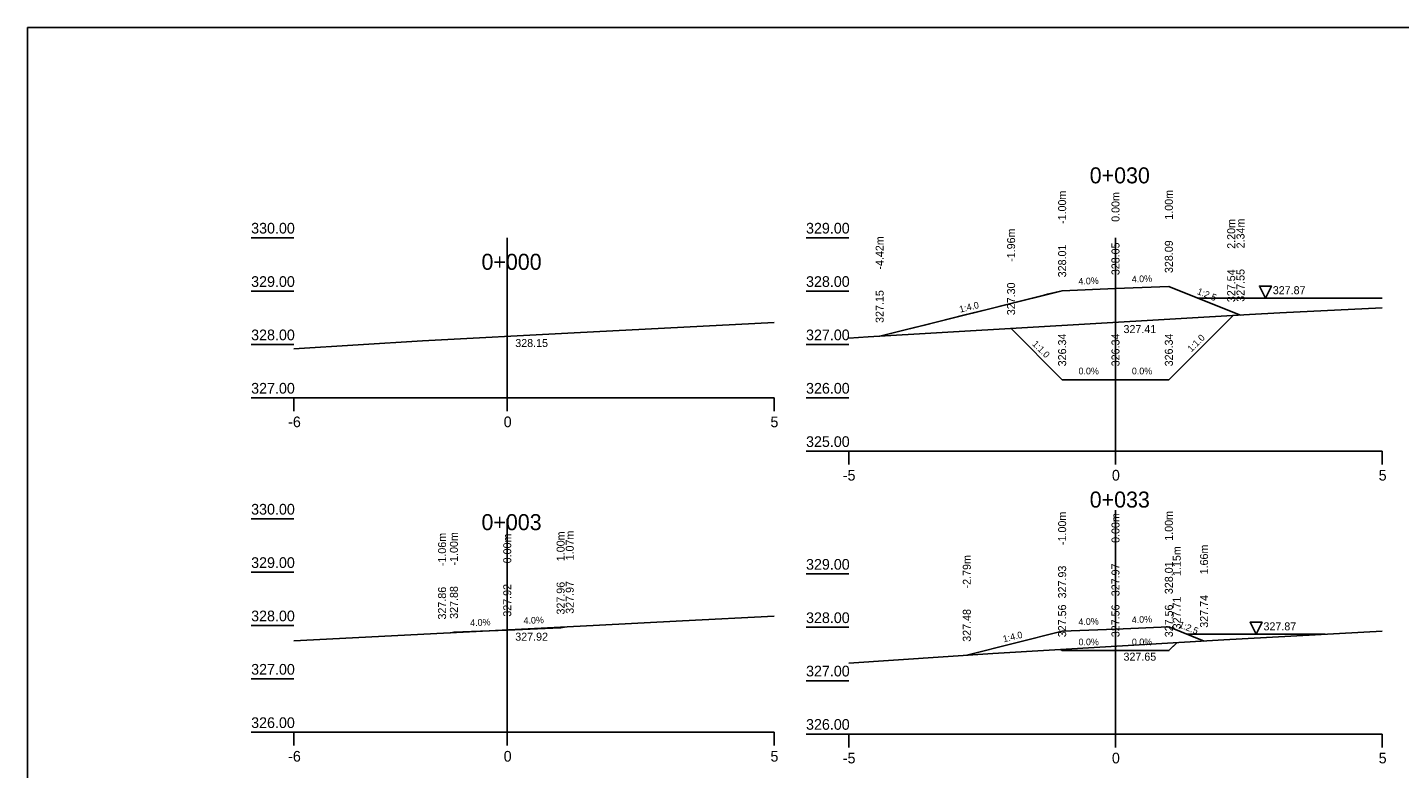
# Model space of a CAD drawing. Extents: x -560209.6 to -560167.6, y -1162747.5 to -1162717.8.
# Drawn here: x -560209.56 to -560183.84, y -1162731.68 to -1162717.79 of the extents above; entities that cross this region are included whole.
import ezdxf

# ---------------------------------------------------------------- set-up
doc = ezdxf.new("R2010")
doc.units = 0
for name, color, linetype in [('16', 7, 'Continuous'), ('21', 7, 'Continuous'), ('28', 7, 'Continuous'), ('59', 7, 'Continuous'), ('Body pricny rez', 7, 'Continuous'), ('Popis pricneho profilu', 7, 'Continuous')]:
    doc.layers.add(name, color=color, linetype=linetype)

msp = doc.modelspace()

# ---------------------------------------------------------------- linework, layer by layer
for p, q in [((-560167.561, -1162717.787), (-560209.561, -1162717.787)), ((-560209.561, -1162717.787), (-560209.561, -1162747.487))]:
    msp.add_line(p, q)
for points in [[(-560193.588, -1162723.575), (-560192.937, -1162723.412), (-560192.748, -1162723.365), (-560192.017, -1162723.182), (-560191.572, -1162723.071), (-560191.177, -1162722.972), (-560190.507, -1162722.805), (-560190.44, -1162722.788), (-560190.168, -1162722.72), (-560189.168, -1162722.68), (-560188.168, -1162722.64), (-560187.716, -1162722.821), (-560186.825, -1162723.177)], [(-560189.168, -1162722.68), (-560190.168, -1162722.72)], [(-560189.168, -1162722.68), (-560188.168, -1162722.64)], [(-560188.168, -1162722.64), (-560186.825, -1162723.177)], [(-560190.168, -1162722.72), (-560193.588, -1162723.575)], [(-560187.619, -1162722.859), (-560184.168, -1162722.859)], [(-560194.168, -1162723.612), (-560193.806, -1162723.588), (-560186.657, -1162723.167), (-560186.087, -1162723.135), (-560184.168, -1162723.044)], [(-560191.125, -1162723.43), (-560190.168, -1162724.388), (-560189.168, -1162724.388), (-560188.168, -1162724.388), (-560186.965, -1162723.185)], [(-560188.168, -1162724.388), (-560186.965, -1162723.185)], [(-560204.568, -1162723.813), (-560202.154, -1162723.657), (-560199.315, -1162723.512), (-560195.568, -1162723.317)], [(-560190.168, -1162724.388), (-560191.125, -1162723.43)], [(-560189.168, -1162724.388), (-560190.168, -1162724.388)], [(-560189.168, -1162724.388), (-560188.168, -1162724.388)], [(-560204.568, -1162729.283), (-560198.958, -1162728.997), (-560197.286, -1162728.91), (-560195.568, -1162728.821)], [(-560201.623, -1162729.133), (-560201.568, -1162729.12), (-560200.568, -1162729.08), (-560199.568, -1162729.04), (-560199.494, -1162729.025)], [(-560201.568, -1162729.12), (-560201.623, -1162729.133)], [(-560200.568, -1162729.08), (-560201.568, -1162729.12)], [(-560200.568, -1162729.08), (-560199.568, -1162729.04)], [(-560199.568, -1162729.04), (-560199.494, -1162729.025)], [(-560194.168, -1162729.699), (-560191.468, -1162729.517), (-560187.138, -1162729.265), (-560184.168, -1162729.099)], [(-560190.168, -1162729.103), (-560191.955, -1162729.55)], [(-560189.168, -1162729.063), (-560190.168, -1162729.103)], [(-560189.168, -1162729.063), (-560188.168, -1162729.023)], [(-560188.168, -1162729.023), (-560187.508, -1162729.287)], [(-560190.19, -1162729.443), (-560190.168, -1162729.465), (-560189.278, -1162729.465), (-560189.168, -1162729.465), (-560188.278, -1162729.465), (-560188.168, -1162729.465), (-560188.132, -1162729.428), (-560188.02, -1162729.317)], [(-560188.168, -1162729.465), (-560188.02, -1162729.317)], [(-560187.827, -1162729.159), (-560185.239, -1162729.159)], [(-560189.168, -1162729.465), (-560190.168, -1162729.465)], [(-560189.168, -1162729.465), (-560188.168, -1162729.465)]]:
    msp.add_lwpolyline(points)
for points in [[(-560186.359, -1162722.859), (-560186.472, -1162722.634), (-560186.247, -1162722.634)], [(-560186.533, -1162729.159), (-560186.645, -1162728.934), (-560186.42, -1162728.934)]]:
    msp.add_lwpolyline(points, close=True)
at = {"layer": '16'}
for p, q in [((-560204.568, -1162724.729), (-560195.568, -1162724.729)), ((-560194.168, -1162725.729), (-560184.168, -1162725.729)), ((-560204.568, -1162730.996), (-560195.568, -1162730.996)), ((-560194.168, -1162731.029), (-560184.168, -1162731.029))]:
    msp.add_line(p, q, dxfattribs=at)
at = {"layer": '21'}
for p, q in [((-560205.368, -1162721.729), (-560204.568, -1162721.729)), ((-560194.968, -1162721.729), (-560194.168, -1162721.729)), ((-560205.368, -1162722.729), (-560204.568, -1162722.729)), ((-560194.968, -1162722.729), (-560194.168, -1162722.729)), ((-560205.368, -1162723.729), (-560204.568, -1162723.729)), ((-560194.968, -1162723.729), (-560194.168, -1162723.729)), ((-560205.368, -1162724.729), (-560204.568, -1162724.729)), ((-560194.968, -1162724.729), (-560194.168, -1162724.729)), ((-560194.968, -1162725.729), (-560194.168, -1162725.729)), ((-560205.368, -1162726.996), (-560204.568, -1162726.996)), ((-560205.368, -1162727.996), (-560204.568, -1162727.996)), ((-560194.968, -1162728.029), (-560194.168, -1162728.029)), ((-560205.368, -1162728.996), (-560204.568, -1162728.996)), ((-560194.968, -1162729.029), (-560194.168, -1162729.029)), ((-560205.368, -1162729.996), (-560204.568, -1162729.996)), ((-560194.968, -1162730.029), (-560194.168, -1162730.029)), ((-560205.368, -1162730.996), (-560204.568, -1162730.996)), ((-560194.968, -1162731.029), (-560194.168, -1162731.029))]:
    msp.add_line(p, q, dxfattribs=at)
at = {"layer": '28'}
for p, q in [((-560200.568, -1162721.729), (-560200.568, -1162724.729)), ((-560189.168, -1162721.729), (-560189.168, -1162725.729)), ((-560200.568, -1162726.996), (-560200.568, -1162730.996)), ((-560189.168, -1162726.833), (-560189.168, -1162731.029))]:
    msp.add_line(p, q, dxfattribs=at)
at = {"layer": '59'}
for p, q in [((-560204.568, -1162724.979), (-560204.568, -1162724.729)), ((-560200.568, -1162724.979), (-560200.568, -1162724.729)), ((-560195.568, -1162724.979), (-560195.568, -1162724.729)), ((-560194.168, -1162725.979), (-560194.168, -1162725.729)), ((-560189.168, -1162725.979), (-560189.168, -1162725.729)), ((-560184.168, -1162725.979), (-560184.168, -1162725.729)), ((-560204.568, -1162731.246), (-560204.568, -1162730.996)), ((-560200.568, -1162731.246), (-560200.568, -1162730.996)), ((-560195.568, -1162731.246), (-560195.568, -1162730.996)), ((-560194.168, -1162731.279), (-560194.168, -1162731.029)), ((-560189.168, -1162731.279), (-560189.168, -1162731.029)), ((-560184.168, -1162731.279), (-560184.168, -1162731.029))]:
    msp.add_line(p, q, dxfattribs=at)

# ---------------------------------------------------------------- texts
for s, height, p in [('0+030', 0.3, (-560189.651, -1162720.709)), ('0+000', 0.3, (-560201.051, -1162722.329)), ('327.87', 0.15, (-560186.22, -1162722.786)), ('0+033', 0.3, (-560189.651, -1162726.785)), ('0+003', 0.3, (-560201.051, -1162727.208)), ('327.87', 0.15, (-560186.394, -1162729.086))]:
    msp.add_text(s, height=height).set_placement(p)
for s, rotation, p in [('1:2.5', 338.1986, (-560187.65, -1162722.78)), ('1:4.0', 14.0362, (-560192.078, -1162723.133)), ('1:1.0', 315, (-560190.737, -1162723.73)), ('1:1.0', 45, (-560187.745, -1162723.877)), ('1:4.0', 14.0362, (-560191.261, -1162729.312)), ('1:2.5', 338.1986, (-560187.992, -1162729.026))]:
    msp.add_text(s, height=0.125, rotation=rotation).set_placement(p)
at = {"layer": '16'}
for s, rotation, p in [('4.0%', 2.2906, (-560188.861, -1162722.568)), ('4.0%', 2.2906, (-560189.861, -1162722.608)), ('4.0%', 2.2906, (-560201.261, -1162729.007)), ('4.0%', 2.2906, (-560200.261, -1162728.967)), ('4.0%', 2.2906, (-560189.861, -1162728.991)), ('4.0%', 2.2906, (-560188.861, -1162728.951)), ('0.0%', 0, (-560188.861, -1162729.365))]:
    msp.add_text(s, height=0.125, rotation=rotation, dxfattribs=at).set_placement(p)
for p in [(-560189.861, -1162724.288), (-560188.861, -1162724.288), (-560189.861, -1162729.365)]:
    msp.add_text('0.0%', height=0.125, dxfattribs=at).set_placement(p)
at = {"layer": '21'}
for s, p in [('330.00', (-560205.368, -1162721.649)), ('329.00', (-560194.968, -1162721.649)), ('329.00', (-560205.368, -1162722.649)), ('328.00', (-560194.968, -1162722.649)), ('328.00', (-560205.368, -1162723.649)), ('327.00', (-560194.968, -1162723.649)), ('327.00', (-560205.368, -1162724.649)), ('326.00', (-560194.968, -1162724.649)), ('-6', (-560204.675, -1162725.279)), ('0', (-560200.635, -1162725.279)), ('5', (-560195.635, -1162725.279)), ('325.00', (-560194.968, -1162725.649)), ('-5', (-560194.279, -1162726.279)), ('0', (-560189.235, -1162726.279)), ('5', (-560184.235, -1162726.279)), ('330.00', (-560205.368, -1162726.916)), ('329.00', (-560205.368, -1162727.916)), ('329.00', (-560194.968, -1162727.949)), ('328.00', (-560205.368, -1162728.916)), ('328.00', (-560194.968, -1162728.949)), ('327.00', (-560205.368, -1162729.916)), ('327.00', (-560194.968, -1162729.949)), ('326.00', (-560205.368, -1162730.916)), ('326.00', (-560194.968, -1162730.949)), ('-6', (-560204.675, -1162731.546)), ('0', (-560200.635, -1162731.546)), ('5', (-560195.635, -1162731.546)), ('-5', (-560194.279, -1162731.579)), ('0', (-560189.235, -1162731.579)), ('5', (-560184.235, -1162731.579))]:
    msp.add_text(s, height=0.2, dxfattribs=at).set_placement(p)
at = {"layer": '59'}
for s, p in [('327.41', (-560189.018, -1162723.515)), ('328.15', (-560200.418, -1162723.776)), ('327.92', (-560200.418, -1162729.28)), ('327.65', (-560189.018, -1162729.654))]:
    msp.add_text(s, height=0.15, dxfattribs=at).set_placement(p)
at = {"layer": 'Body pricny rez'}
for p in [(-560189.168, -1162722.68), (-560188.168, -1162722.64), (-560190.168, -1162722.72), (-560186.966, -1162723.186), (-560186.825, -1162723.178), (-560191.126, -1162723.431), (-560193.589, -1162723.575), (-560190.168, -1162724.388), (-560189.168, -1162724.388), (-560188.168, -1162724.388), (-560201.623, -1162729.134), (-560201.568, -1162729.12), (-560200.568, -1162729.08), (-560199.568, -1162729.04), (-560199.495, -1162729.025), (-560190.168, -1162729.103), (-560189.168, -1162729.063), (-560188.168, -1162729.023), (-560188.02, -1162729.317), (-560187.509, -1162729.287), (-560191.956, -1162729.55), (-560190.168, -1162729.465), (-560189.168, -1162729.465), (-560188.168, -1162729.465)]:
    msp.add_text('+', height=0.001, dxfattribs=at).set_placement(p)
at = {"layer": 'Popis pricneho profilu'}
for s, p in [('-1.00m', (-560190.093, -1162721.47)), ('0.00m', (-560189.093, -1162721.43)), ('1.00m', (-560188.093, -1162721.39)), ('2.20m', (-560186.924, -1162721.935)), ('2.34m', (-560186.75, -1162721.927)), ('-1.96m', (-560191.05, -1162722.18)), ('-4.42m', (-560193.513, -1162722.325)), ('328.01', (-560190.093, -1162722.47)), ('328.05', (-560189.093, -1162722.43)), ('328.09', (-560188.093, -1162722.39)), ('327.54', (-560186.924, -1162722.935)), ('327.55', (-560186.75, -1162722.927)), ('327.30', (-560191.05, -1162723.18)), ('327.15', (-560193.513, -1162723.325)), ('326.34', (-560190.093, -1162724.138)), ('326.34', (-560189.093, -1162724.138)), ('326.34', (-560188.093, -1162724.138)), ('-1.00m', (-560190.093, -1162727.487)), ('0.00m', (-560189.093, -1162727.447)), ('1.00m', (-560188.093, -1162727.407)), ('-1.06m', (-560201.715, -1162727.883)), ('-1.00m', (-560201.493, -1162727.87)), ('0.00m', (-560200.493, -1162727.83)), ('1.00m', (-560199.493, -1162727.79)), ('1.07m', (-560199.322, -1162727.775)), ('1.15m', (-560187.945, -1162728.067)), ('1.66m', (-560187.433, -1162728.037)), ('-2.79m', (-560191.88, -1162728.3)), ('327.97', (-560189.093, -1162728.447)), ('328.01', (-560188.093, -1162728.407)), ('327.93', (-560190.093, -1162728.487)), ('327.86', (-560201.715, -1162728.883)), ('327.88', (-560201.493, -1162728.87)), ('327.92', (-560200.493, -1162728.83)), ('327.96', (-560199.493, -1162728.79)), ('327.97', (-560199.322, -1162728.775)), ('327.56', (-560190.093, -1162729.215)), ('327.56', (-560189.093, -1162729.215)), ('327.56', (-560188.093, -1162729.215)), ('327.71', (-560187.945, -1162729.067)), ('327.74', (-560187.433, -1162729.037)), ('327.48', (-560191.88, -1162729.3))]:
    msp.add_text(s, height=0.15, rotation=90, dxfattribs=at).set_placement(p)

doc.saveas('drawing.dxf')
